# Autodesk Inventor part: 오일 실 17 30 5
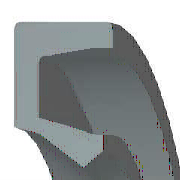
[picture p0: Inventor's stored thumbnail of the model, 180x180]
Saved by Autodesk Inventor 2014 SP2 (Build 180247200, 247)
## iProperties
IsCustomPart: 1
Created: 2012-02
Part Number: 오일 실 17 30 5
Material: 고무
Description: 오일 실 - 비스프링, 금속 케이스 GM
Document SubType Name: Modeling
Standard: JIS B 2402
Designer: mduedu
Standards Organization: JIS
Language: ko-KR
Size Designation: 17 30 5 B
Categories: <MemberInstance><Categories><Category DisplayName="샤프트 부품" InternalName="7f7aeb1f-a693-4053-b835-cee3144e0d98" Mnemonic="SHFT"><Category DisplayName="실링" Intern
Density: 0.93 g/cm^3
Appearance: Rubber-Black
Author: mduedu
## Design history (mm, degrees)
body "Solid1"
revolve "회전1" stored, may be unused: angle "d27" = 360 deg
fillet "모깎기1" dims "d28" = 0.25 (= 0.05 x b)
chamfer "모따기1" distance "d29" = 0.07143 (= 0.0142857 x b); stored, may be unused: second distance "d30" = 0.25 (= 0.05 x b), angle "d35" = 45 deg
sketch "스케치2"
  geometry: L1 (-9.367, -3.238)-(-10.233, -3.863); L2 (-8.5, -1.625)-(-9.367, -3.238); L3 (-9.15, -1)-(-8.5, -1.625); L4 (-11.317, -3.75)-(-9.15, -1); L5 (-13.075, -3.75)-(-11.317, -3.75); L6 (-14.375, -1.25)-(-13.075, -3.75); L7 (-14.375, 0)-(-14.375, -1.25); L8 (-15, 0)-(-14.375, 0); L9 (-15, -5)-(-15, 0); L10 (-11.129, -5)-(-15, -5); L11 (-10.233, -3.863)-(-11.129, -5); L12 (0, -9.6)-(0, 1.6) reference; L13 (-14, 0)-(-28, 0) reference
  constraints: 22 end point, 3 horizontal, 2 vertical, 1 parallel
  dimensions: "d2" = 5 distance of L9.start L8.start (= b); "d4" = 1 vertical distance of L8.start L3.start (= 0.2 x b); "d6" = 0.625 distance of L8.start L7.start (= 0.125 x b); "d8" = 1.25 distance of L7.start L6.start (= 0.25 x b); "d10" = 1.25 vertical distance of L5.start L9.start (= 0.25 x b); "d12" = 1.3 horizontal distance of L6.start L5.start (= 0.1 x dd - 0.1 x Diam); "d14" = 1.6129 vertical distance of L2.start L1.start (= 0.322581 x b); "d16" = 0.86667 horizontal distance of L1.start L1.end (= 0.0666667 x dd - 0.0666667 x Diam); "d18" = 0.86667 horizontal distance of L2.start L1.start (= 0.0666667 x dd - 0.0666667 x Diam); "d20" = 0.625 vertical distance of L3.start L2.start (= 0.125 x b); "d22" = 0.65 horizontal distance of L3.start L2.start (= 0.05 x dd - 0.05 x Diam); "d24" = 0.625 vertical distance of L1.start L1.end (= 0.125 x b); "d26" = 2.16667 horizontal distance of L4.start L3.start (= 0.166667 x dd - 0.166667 x Diam); "d31" = 0 distance between parallel lines of L8 L13; "d32" = 15 distance between parallel lines of L12 L9 (= 0.5 x dd); "d33" = 8.5 distance from line of L12 L2.start (= 0.5 x Diam)
other parameters: "Diam" = 17 [user parameter; used in 6 equation terms], "b" = 5 [user parameter; used in 11 equation terms], "d1" = 8 (derived), "d3" = 1.6 (derived), "d5" = 1 (derived), "d7" = 2 (derived), "d9" = 2 (derived), "d11" = 2 (derived), "d13" = 2.58065 (derived), "d15" = 1.33333 (derived), "d17" = 1.33333 (derived), "d19" = 1 (derived), "d21" = 1 (derived), "d23" = 1 (derived), "d25" = 3.33333 (derived), "d34" = 0
